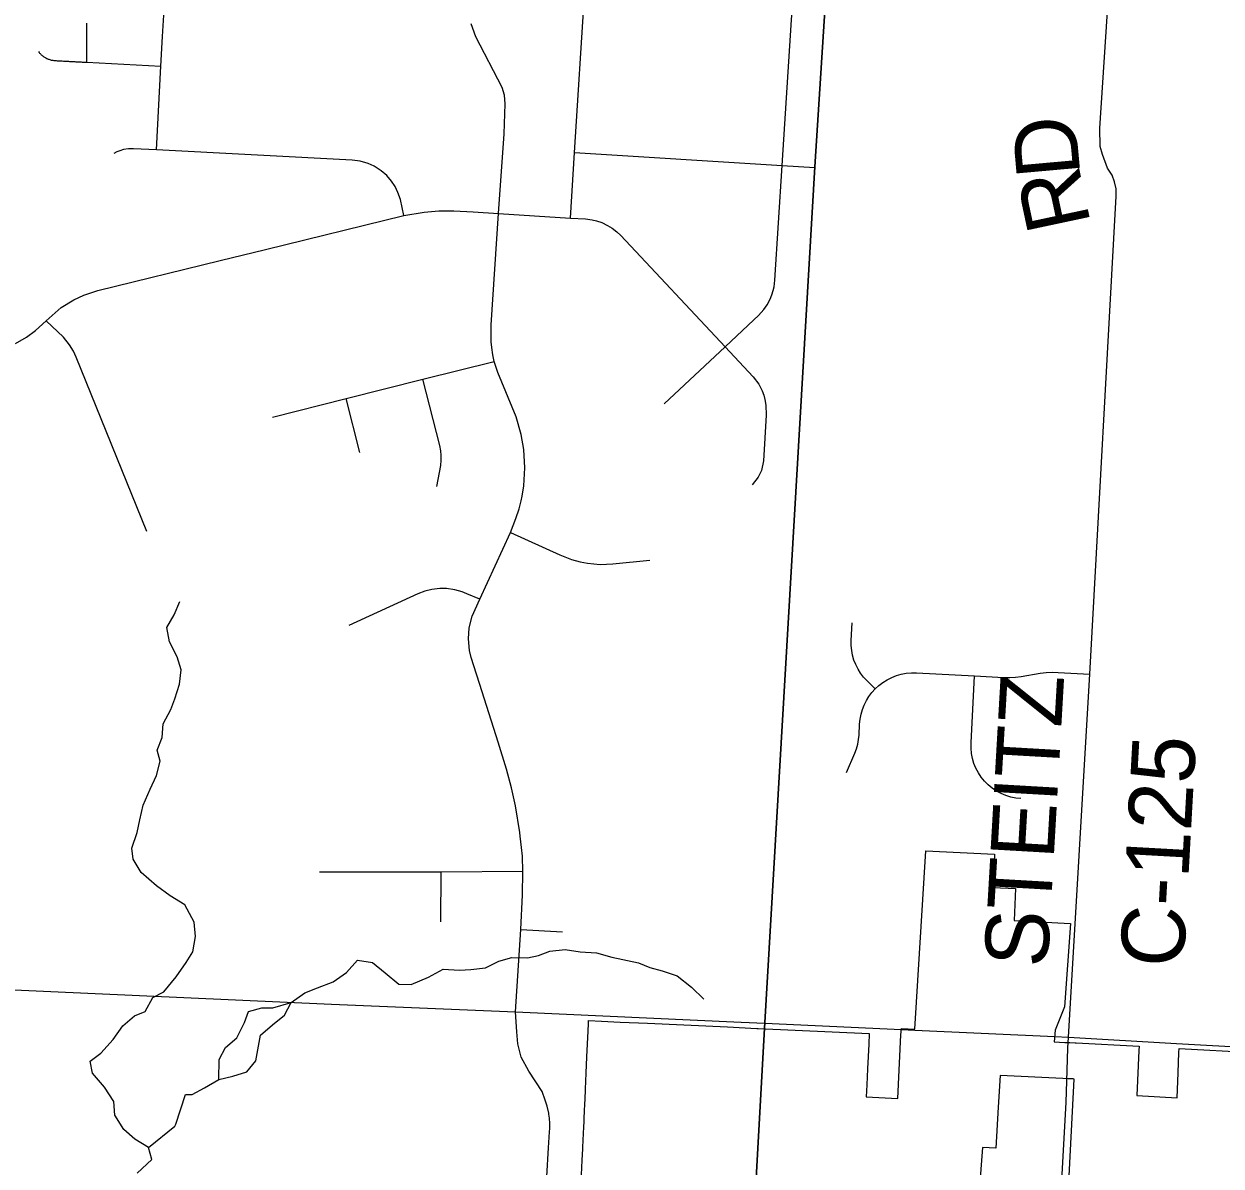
# Model space of a CAD drawing. Extents: x 114604 to 551442, y 316898 to 567001.
# Drawn here: x 170261 to 175916, y 471660 to 477053 of the extents above; entities that cross this region are included whole.
import ezdxf

# ---------------------------------------------------------------- set-up
doc = ezdxf.new("R2010")
doc.units = 0
for name, color, linetype in [('GE_P_Alignment_1000_Cardinal_Points', 7, 'Continuous'), ('GE_P_Alignment_100_Stations', 7, 'Continuous'), ('GE_P_Alignment_500_Bearings', 7, 'Continuous'), ('GE_P_Alignment_500_Distances', 7, 'Continuous'), ('PM_P_Cells', 7, 'Continuous'), ('PM_P_CL_Double_Solid', 7, 'Continuous')]:
    doc.layers.add(name, color=color, linetype=linetype)

msp = doc.modelspace()

# ---------------------------------------------------------------- linework, layer by layer
at = {"layer": 'GE_P_Alignment_1000_Cardinal_Points'}
for p, q in [((171848.1, 475029), (171783.9, 475284.1)), ((172231.2, 472813.8), (172232.2, 473047.4)), ((172608.2, 472776.6), (172804.7, 472766.6)), ((175193.1, 472216.7), (175195, 472268.9)), ((175187.6, 472060.4), (175193.1, 472216.7))]:
    msp.add_line(p, q, dxfattribs=at)
for points in [[(172843.1, 476136.9), (172862.4, 476446.3), (172910.3, 477212.4), (172945.4, 477774.7), (172956.3, 477948.8), (172959.2, 477971.1), (172964.5, 477991.9), (172975.7, 478018.8), (172992.2, 478044.6), (173011.7, 478069.6)], [(173285.1, 475258.6), (173573.1, 475528.9), (173708.8, 475656.2), (173730.4, 475676.5), (173756.8, 475705.5), (173771.7, 475727), (173786.2, 475753.9), (173794.5, 475774.1), (173801, 475794.9), (173804.9, 475811.9), (173808.8, 475842.8), (173843.5, 476385), (173887.7, 477072.9), (173911.7, 477392.7), (173922.6, 477562.9), (173932.2, 477712), (173952.7, 478031.4)], [(170887.7, 476458.2), (170908.4, 476854), (170915.7, 476993.6), (170921.8, 477094.7)], [(170558.9, 476872.3), (170558.9, 476877.3), (170558.9, 476882.3), (170558.9, 476887.3), (170558.9, 476892.2), (170558.8, 476897.2), (170558.8, 476902.2), (170558.8, 476907.1), (170558.8, 476912.1), (170558.8, 476917.1), (170558.8, 476922.1), (170558.8, 476927.1), (170558.8, 476932), (170558.8, 476937), (170558.8, 476942), (170558.8, 476946.9), (170558.8, 476951.9), (170558.8, 476956.9), (170558.8, 476961.9), (170558.7, 476966.8), (170558.7, 476971.8), (170558.7, 476976.8), (170558.7, 476981.7), (170558.7, 476986.7), (170558.7, 476991.7), (170558.7, 476996.7), (170558.7, 477001.6), (170558.7, 477006.6), (170558.7, 477011.6), (170558.7, 477016.6), (170558.7, 477021.5), (170558.7, 477026.5), (170558.7, 477031.5), (170558.7, 477036.4), (170558.7, 477041.4), (170558.7, 477046.4), (170558.7, 477051.4), (170558.7, 477056.3)], [(172605.8, 473218), (172603.8, 473235.8), (172583, 473360.6), (172564.7, 473445.8), (172541.2, 473534.2), (172501.2, 473661.5), (172426.6, 473899.7), (172374.1, 474061.9), (172365.7, 474094), (172360.8, 474149.3), (172364.6, 474201), (172379.1, 474256), (172414.9, 474337.5), (172559, 474651.3), (172585.4, 474717.3), (172600.4, 474764.1), (172609.5, 474801.2), (172614.6, 474823.8), (172622.1, 474872.2), (172627.2, 474957.7), (172622.1, 475043.1), (172609.5, 475115.3), (172585.7, 475197.4), (172499.7, 475407.4), (172483.3, 475460), (172476.5, 475491.4), (172471.4, 475525.9), (172469.1, 475552), (172468.2, 475586.9), (172468.9, 475632.4), (172503.3, 476158.1), (172529.6, 476534.1), (172534.6, 476676.7), (172531, 476716.4), (172521, 476752.8), (172395.7, 476992.3), (172373.4, 477054.1)], [(170329.6, 476922.4), (170332.6, 476918.6), (170335.2, 476915.7), (170337.8, 476913), (170340.5, 476910.3), (170343.4, 476907.7), (170346.3, 476905.2), (170349.3, 476902.8), (170352.4, 476900.5), (170355.6, 476898.3), (170358.8, 476896.3), (170362.1, 476894.3), (170365.5, 476892.5), (170368.9, 476890.7), (170372.4, 476889.1), (170375.9, 476887.6), (170379.5, 476886.3), (170383.2, 476885.1), (170386.9, 476884), (170390.6, 476883), (170394.3, 476882.2), (170398.1, 476881.5), (170401.9, 476880.9), (170405.7, 476880.5), (170409.5, 476880.2), (170413.1, 476880), (170418, 476879.7), (170423, 476879.5), (170427.9, 476879.2), (170432.9, 476878.9), (170437.8, 476878.7), (170442.7, 476878.4), (170447.7, 476878.2), (170452.6, 476877.9), (170457.6, 476877.6), (170462.5, 476877.4), (170467.5, 476877.1), (170472.4, 476876.9), (170477.3, 476876.6), (170482.3, 476876.3), (170487.2, 476876.1), (170492.1, 476875.8), (170497.1, 476875.6), (170502, 476875.3), (170507, 476875.1), (170511.9, 476874.8), (170516.9, 476874.6), (170521.8, 476874.3), (170526.7, 476874), (170531.7, 476873.8), (170536.6, 476873.5), (170541.6, 476873.3), (170546.5, 476873), (170551.5, 476872.7), (170558.9, 476872.3), (170908.4, 476854)], [(172056, 476149.1), (172039.5, 476224.9), (172028.1, 476257.8), (172014.5, 476285.2), (171997.7, 476310.6), (171974.8, 476336.9), (171948.4, 476359.8), (171915.3, 476380.9), (171887.6, 476393.5), (171850, 476404.7), (171811.2, 476409.8), (170887.7, 476458.2), (170779.6, 476463.8), (170755.4, 476463.4), (170731.6, 476459.6), (170714.1, 476454.6), (170700.1, 476449.1), (170686.3, 476442.2)], [(172862.4, 476446.3), (173843.5, 476385), (173998, 476375.3)], [(170221, 475544.3), (170274.1, 475574.4), (170316.4, 475605.2), (170365.8, 475651.1), (170437.6, 475714.2), (170496.9, 475751), (170544.4, 475773), (170610.8, 475794.3), (171188.6, 475936.4), (171402.3, 475988.9), (172056, 476149.1), (172152.3, 476164.8), (172221.9, 476170.2), (172291.7, 476170.8), (172383.5, 476165.6), (172503.3, 476158.1)], [(172503.3, 476158.1), (172843.1, 476136.9), (172913.6, 476132.5), (172944.9, 476128.5), (172966.1, 476123.5), (172990.9, 476115.1), (173018.5, 476102), (173040.7, 476088.2), (173061.4, 476072.2), (173080.3, 476054.1), (173573.1, 475528.9), (173706.2, 475387), (173732, 475351.8), (173748, 475320.9), (173755.8, 475300.5), (173761.7, 475279.5), (173766.4, 475253.8), (173767.9, 475205.9), (173754.1, 474990.4), (173745.1, 474945.3), (173729.9, 474912.5), (173701.8, 474877.1)], [(170842.4, 474656), (170508.7, 475479.1), (170495.4, 475507.5), (170476.3, 475538.7), (170447.5, 475573.7), (170365.8, 475651.1)], [(171435.3, 475196.5), (171783.9, 475284.1), (172145.8, 475375.1), (172483.3, 475460)], [(172212, 474869.6), (172230.6, 474967.6), (172232.8, 474993.6), (172232.7, 475015.4), (172230.5, 475037.1), (172225.5, 475063.3), (172145.8, 475375.1)], [(172559, 474651.3), (172792.2, 474546.5), (172847.8, 474524.2), (172888.4, 474513.4), (172924, 474506.4), (172983.6, 474501.1), (173043.1, 474503.3), (173218, 474520.8)], [(172414.9, 474337.5), (172353.2, 474361.5), (172330.9, 474370.8), (172296.8, 474381.4), (172256.9, 474388), (172226.1, 474387.8), (172187.9, 474383.2), (172155, 474375.2), (172121.6, 474362.4), (171796, 474212.4)], [(174282.1, 473913.1), (174243.7, 473950.9), (174227.8, 473968.2), (174213.6, 473986.8), (174201.2, 474006.7), (174190.7, 474027.7), (174182.2, 474049.6), (174175.8, 474072.1), (174171.5, 474095.2), (174169.5, 474118.6), (174169.6, 474142), (174173.9, 474224.9)], [(174282.1, 473913.1), (174299.7, 473929.4), (174318.7, 473943.9), (174339, 473956.5), (174360.4, 473967.2), (174382.7, 473975.9), (174405.7, 473982.4), (174429.2, 473986.8), (174453.1, 473988.9), (174477, 473988.8), (174751.6, 473974.4), (174890.4, 473967.1), (174917.6, 473966.7), (174944.7, 473968.2), (174971.7, 473971.7), (175062.4, 473986.9), (175090.1, 473990.4), (175118, 473991.9), (175145.9, 473991.3), (175296.4, 473982.5)], [(174971, 473395.1), (174946.7, 473397.7), (174922.7, 473402.6), (174899.3, 473409.8), (174876.7, 473419.3), (174855.1, 473431), (174834.8, 473444.7), (174816, 473460.3), (174798.7, 473477.7), (174783.3, 473496.7), (174769.8, 473517.1), (174758.3, 473538.8), (174749, 473561.4), (174742, 473584.9), (174737.3, 473608.9), (174735, 473633.3), (174735.1, 473657.8), (174751.6, 473974.4)], [(174147.3, 473518.4), (174186.6, 473610.4), (174194.3, 473630.9), (174200.2, 473652.1), (174204.2, 473673.6), (174206.3, 473695.5), (174209, 473747.4), (174211.3, 473770.4), (174215.6, 473793.2), (174222, 473815.4), (174230.4, 473837), (174240.6, 473857.7), (174252.8, 473877.4), (174266.6, 473895.9), (174282.1, 473913.1)], [(172583.9, 472387.6), (172608.2, 472776.6), (172615.9, 472940.7), (172617.3, 473050.9), (172615.8, 473122.6), (172611.8, 473164.9), (172605.8, 473218)], [(172617.3, 473050.9), (172232.2, 473047.4), (171657.8, 473047)], [(172740.8, 471904.9), (172740.1, 471909.8), (172732.9, 471942.7), (172724.2, 471970.7), (172709.3, 472011.8), (172646.5, 472107.5), (172610.5, 472174.8), (172606.7, 472186.9), (172603.2, 472199.1), (172598.7, 472217.6), (172595, 472236.5), (172592.3, 472255.5), (172590.5, 472274.7), (172589.6, 472294.1), (172583.9, 472387.6)], [(175010.2, 468721.6), (175026.9, 469002.7), (175145.3, 471370.7), (175165.5, 471619.3), (175184.1, 471961.3), (175187.6, 472060.4)], [(172731.4, 471610.4), (172738.8, 471745.8), (172744.7, 471822.2), (172745.4, 471836.7), (172745.2, 471861.1), (172743.4, 471885.5), (172740.8, 471904.9)]]:
    msp.add_lwpolyline(points, dxfattribs=at)
at = {"layer": 'GE_P_Alignment_100_Stations'}
for points in [[(172894.7, 471618.3), (172898.4, 471688.1), (172901.2, 471741.2), (172902, 471758.3), (172902.5, 471770.6), (172905, 471824.4), (172905.4, 471834.7), (172909.5, 471925.2), (172910.5, 471947.2), (172913.6, 472015.6), (172913.9, 472023.7), (172917.3, 472098.9), (172920.7, 472175.1), (172926.2, 472296.9), (172927.8, 472333.8), (172928.4, 472347.1), (172990.2, 472344), (173077.7, 472340), (173207, 472334), (173584.9, 472316.7), (173723.5, 472310.3), (173729.4, 472310.1), (174254.4, 472285.9), (174251.9, 472236.1), (174246, 472119.1), (174242.2, 472043.1), (174239.4, 471986.9), (174389.2, 471979.4), (174404.2, 472279.1), (174406, 472309), (174470.1, 472306.1), (174521.4, 473148), (174846.2, 473132.4), (174840.3, 472974.8), (174945.4, 472970.3), (174939.6, 472819.8), (175205.1, 472805.4), (175176, 472412), (175132.3, 472301.9), (175127.4, 472245.9), (175177.4, 472243.6), (175201.3, 472242.9), (175226.3, 472242.1), (175231.2, 472241.9), (175529.5, 472225.9), (175528.5, 472205.5), (175518.3, 471993.6), (175709.5, 471982.3), (175713.7, 472099.5), (175717.2, 472195.7), (175717.9, 472215.7), (176066.8, 472196.8)], [(175196.2, 471552.2), (175222.6, 472070.9), (175217.6, 472071.1), (175192.6, 472072.4), (175168.3, 472073.7), (174872.4, 472088.3), (174863.6, 471937.5), (174852.2, 471744.9), (174789.6, 471747.6), (174784.9, 471686.6), (174778.4, 471603.2)]]:
    msp.add_lwpolyline(points, dxfattribs=at)
at = {"layer": 'GE_P_Alignment_500_Bearings'}
for p, q in [((174406.3, 472304.9), (174470.2, 472301.9)), ((174470.2, 472301.9), (175131, 472271.8))]:
    msp.add_line(p, q, dxfattribs=at)
for points in [[(175195, 472268.9), (175296.4, 473982.5), (175421.2, 476239.4), (175420.3, 476274.4), (175413.5, 476308.1), (175401, 476339.4), (175380.5, 476372.5), (175355.4, 476436), (175345, 476475), (175343, 476560.4), (175491.8, 478815.7), (175556.2, 479727.9)], [(168015.6, 472609.8), (168203.3, 472640.7), (168285.7, 472660.1), (168392.8, 472691.1), (168426.4, 472696.7), (168500.2, 472699.2), (168546.7, 472664.7), (168603.4, 472624.1), (168660.6, 472595.7), (168731.3, 472570.7), (168787.8, 472558.4), (168926.1, 472545.9), (169445.3, 472527.4), (171714.5, 472424.7), (172583.9, 472387.6), (173649.6, 472339.4)], [(173649.6, 472339.4), (173761.5, 472334.3), (174406.3, 472304.9)], [(175131, 472271.8), (175195, 472268.9), (175706.1, 472238.6), (178864.6, 472064.5)]]:
    msp.add_lwpolyline(points, dxfattribs=at)
at = {"layer": 'GE_P_Alignment_500_Distances'}
for points in [[(169905.4, 461946.5), (169968.1, 464386.5), (169947, 464678.7), (169899, 465343.8), (169749.8, 465987.7), (169587.5, 466795.7), (170734.8, 466733), (170828.3, 466720.5), (173439.3, 466568.9), (173760.3, 472337.1), (173996.9, 476378.2), (174122.9, 478346.3)], [(174122.9, 478346.3), (173996.9, 476378.2), (173760.3, 472337.1), (173439.3, 466568.9), (170828.3, 466720.5), (170734.8, 466733), (169587.5, 466795.7), (169749.8, 465987.7), (169899, 465343.8), (169947, 464678.7), (169968.1, 464386.5), (169905.4, 461946.5)]]:
    msp.add_lwpolyline(points, dxfattribs=at)
at = {"layer": 'PM_P_Cells'}
for points in [[(170795.5, 471627), (170865.4, 471691.4), (170849.1, 471747.4), (170784.8, 471787.1), (170732.5, 471833), (170690.1, 471900.9), (170685.8, 471964.9), (170641.4, 472032.8), (170585, 472098.7), (170574.8, 472154.7), (170624.7, 472192.9), (170682.6, 472257.3), (170728.4, 472321.5), (170784.3, 472369.8), (170834.4, 472390.1), (170870.1, 472456.3), (170922.2, 472482.6), (170980, 472552.9), (171027.8, 472621.2), (171059.7, 472671.4), (171071.4, 472743.6), (171065.1, 472811.6), (171020.6, 472893.6), (170952.3, 472935.3), (170887.9, 472983.1), (170815.5, 473046.9), (170777.1, 473108.8), (170770.9, 473160.9), (170796.6, 473235.1), (170808.4, 473295.3), (170824.1, 473363.4), (170857.9, 473439.7), (170887.7, 473503.9), (170905.4, 473572.1), (170891.2, 473624.1), (170915, 473684.3), (170918.7, 473748.4), (170954.5, 473816.7), (170974.3, 473866.9), (170996.1, 473935.1), (171003.8, 474003.2), (170985.5, 474065.3), (170949.1, 474135.2), (170936.8, 474203.3), (170970.6, 474263.6), (170998.4, 474325.8)], [(171523, 472431.9), (171588.6, 472478.4), (171648.4, 472500.8), (171722.1, 472529.4), (171785.7, 472573.8), (171837.2, 472632.2), (171907.3, 472620.7), (171967.6, 472573.1), (172031.9, 472519.5), (172089.9, 472517.9), (172171.6, 472552.5), (172241.2, 472589), (172319.2, 472585.5), (172373.1, 472587.9), (172441, 472596.4), (172504.7, 472626.8), (172566.5, 472645.3), (172640.5, 472643.8), (172692.4, 472654.2), (172746.2, 472674.5), (172818, 472683), (172888.1, 472671.5), (172966.1, 472666.1), (173038.1, 472646.5), (173164.3, 472619.4), (173218.4, 472597.8), (173276.4, 472582.2), (173346.6, 472558.6), (173414.9, 472505.1), (173473.3, 472447.4)], [(171182, 472069.4), (171247.8, 472083.8), (171313.6, 472104.3), (171357.2, 472156.6), (171366.8, 472208.7), (171378.3, 472278.8), (171435.8, 472327.3), (171491.5, 472371.7), (171523, 472431.9)], [(171182, 472069.4), (171183.3, 472163.4), (171212.8, 472219.7), (171266.4, 472266.1), (171303.9, 472338.4), (171321.5, 472390.5), (171385.3, 472407), (171437.2, 472407.3), (171523, 472431.9)], [(171024.1, 471998.4), (171056.6, 471998.5), (171114.3, 472028.9), (171182, 472069.4)], [(170849.1, 471747.4), (170974, 471847.9), (170978.9, 471858.1), (171024.1, 471998.4)]]:
    msp.add_lwpolyline(points, dxfattribs=at)

# ---------------------------------------------------------------- texts
at = {"layer": 'PM_P_CL_Double_Solid'}
for s, rotation, p in [('D', 95.1082, (175251.8, 476341.2)), ('R', 102.0232, (175301.7, 476109.7)), ('STEITZ', 86.7083, (175095.9, 472593.5)), ('C-125', 86.8364, (175738.3, 472593.2))]:
    msp.add_text(s, height=300, rotation=rotation, dxfattribs=at).set_placement(p)

doc.saveas('drawing.dxf')
